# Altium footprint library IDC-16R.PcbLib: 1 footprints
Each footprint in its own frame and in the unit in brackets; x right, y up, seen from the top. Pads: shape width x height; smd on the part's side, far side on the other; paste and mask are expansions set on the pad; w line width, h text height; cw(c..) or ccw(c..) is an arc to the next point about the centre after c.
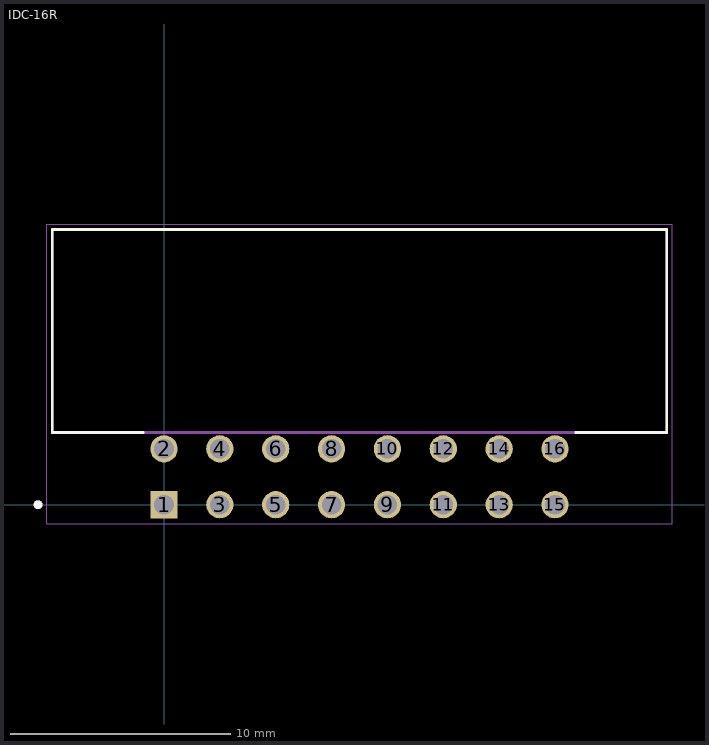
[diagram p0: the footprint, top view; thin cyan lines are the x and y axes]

## IDC-16R [mm]
pads (16):
  rect 1.24x1.24 hole 0.89: 1(0,0)
  round 1.24 hole 0.89: 2(0,2.54) 3(2.54,0) 4(2.54,2.54) 5(5.08,0) 6(5.08,2.54) 7(7.62,0) 8(7.62,2.54) 9(10.16,0) 10(10.16,2.54) 11(12.7,0) 12(12.7,2.54) 13(15.24,0) 14(15.24,2.54) 15(17.78,0) 16(17.78,2.54)
Top Overlay:
  circle w0.2: c-5.73,0 r0.1
  lines w0.127: -0.94,3.29 -5.08,3.29 -5.08,12.51 22.86,12.51 22.86,3.29 18.72,3.29
Mechanical 13:
  circle w0.2: c-5.73,0 r0.1
  lines w0.127: -5.08,3.29 -5.08,12.51 ; -5.08,3.29 22.86,3.29 ; -5.08,3.29 -5.08,12.51 ; -5.08,12.51 22.86,12.51 ; -5.08,12.51 22.86,12.51 ; 22.86,3.29 22.86,12.51 ; 22.86,3.29 22.86,12.51
Mechanical 15:
  lines w0.05: -5.33,-0.87 23.11,-0.87 23.11,12.76 -5.33,12.76 -5.33,-0.87
3D body "IDC-16R.STEP": height 0, standoff -12.51, extent -3.302,-3.937 24.638,7.874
